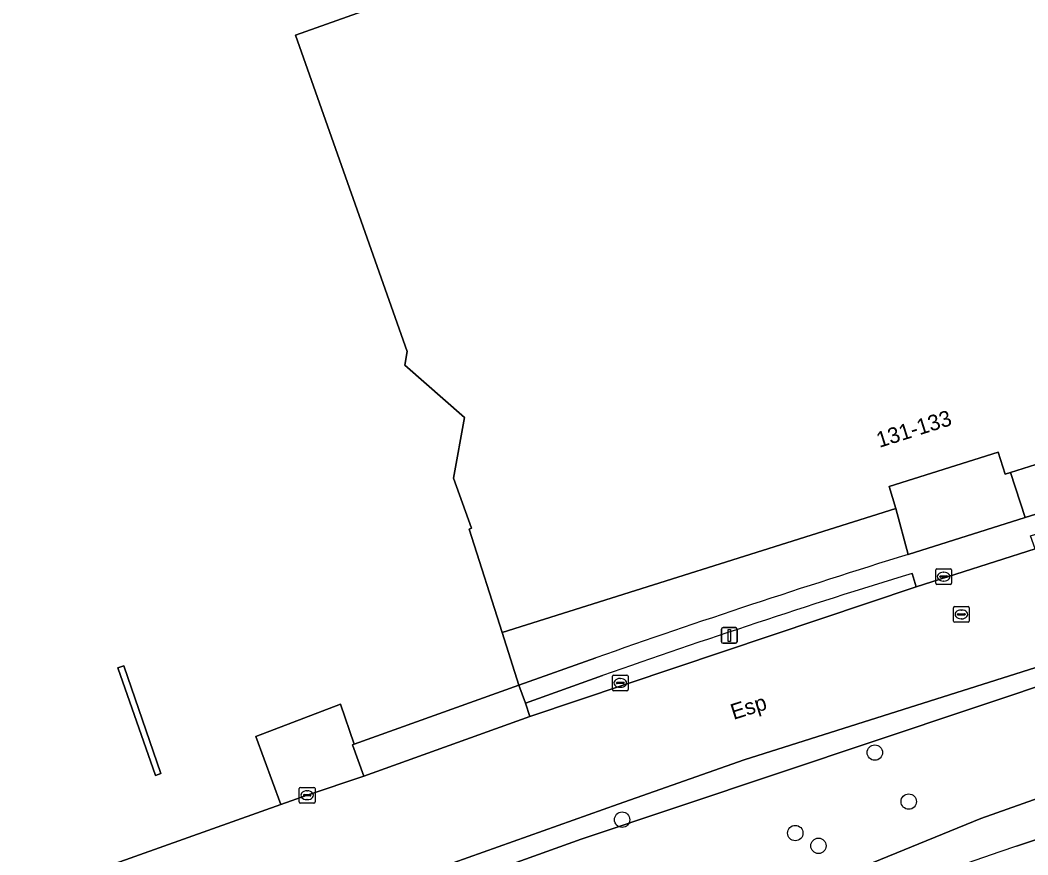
# Model space of a CAD drawing. Extents: x 161385 to 162589, y 388479 to 389756.
# Drawn here: x 162179.9 to 162244, y 388545.6 to 388598.7 of the extents above; entities that cross this region are included whole.
import ezdxf

# ---------------------------------------------------------------- set-up
doc = ezdxf.new("R2010")
doc.units = 0
for name, color, linetype in [('IMGEO_Berm_groen', 7, 'Continuous'), ('IMGEO_Boom', 7, 'Continuous'), ('IMGEO_Erf', 7, 'Continuous'), ('IMGEO_Fietspad_gesloten', 7, 'Continuous'), ('IMGEO_Groenvoorziening', 7, 'Continuous'), ('IMGEO_Kolk', 7, 'Continuous'), ('IMGEO_Lichtmast', 7, 'Continuous'), ('IMGEO_Loofbos', 7, 'Continuous'), ('IMGEO_Muur', 7, 'Continuous'), ('IMGEO_Openbare_ruimte_label', 7, 'Continuous'), ('IMGEO_Pand', 7, 'Continuous'), ('IMGEO_Pand_nummerreeks', 7, 'Continuous'), ('IMGEO_Rijbaan_lokaal_gesloten', 7, 'Continuous'), ('IMGEO_Rioolput', 7, 'Continuous'), ('IMGEO_Voetpad_open', 7, 'Continuous')]:
    doc.layers.add(name, color=color, linetype=linetype)

msp = doc.modelspace()

# ---------------------------------------------------------------- linework, layer by layer
at = {"layer": 'IMGEO_Berm_groen'}
for points in [[(162319.902, 388581.48), (162316.848, 388580.491), (162315.105, 388579.927), (162225.932, 388551.675), (162217.932, 388548.854), (162137.852, 388520.378), (162138.38, 388518.892), (162215.574, 388546.64), (162252.986, 388559.158)], [(162338.365, 388578.901), (162338.047, 388580.195), (162324.599, 388576.081), (162287.169, 388563.505), (162279.038, 388561.214), (162264.796, 388556.642), (162259.025, 388554.101), (162254.71, 388552.825), (162240.969, 388547.955), (162222.876, 388540.549), (162201.4, 388532.175), (162133.055, 388506.534)], [(162243.228, 388546.187), (162337.031, 388577.446)], [(162236.864, 388562.675), (162236.595, 388563.529)], [(162216.931, 388557.029), (162212.031, 388555.28), (162212.321, 388554.419), (162236.864, 388562.675)]]:
    msp.add_lwpolyline(points, dxfattribs=at)
for centre, radius, start, end in [((162387.997, 388072.509), 513.832, 107.13672, 109.44623), ((162557.7, 387632.601), 966.195, 108.994345, 111.094346)]:
    msp.add_arc(centre, radius, start, end, dxfattribs=at)
at = {"layer": 'IMGEO_Boom'}
for centre in [(162234.235, 388552.135), (162236.386, 388549.021), (162218.176, 388547.871), (162229.179, 388547.02), (162230.651, 388546.208)]:
    msp.add_circle(centre, 0.489, dxfattribs=at)
at = {"layer": 'IMGEO_Erf'}
msp.add_lwpolyline([(162178.209, 388542.32), (162196.492, 388548.826), (162194.908, 388553.162), (162200.279, 388555.209), (162201.155, 388552.675), (162211.615, 388556.411), (162210.55, 388559.766), (162208.456, 388566.345), (162208.618, 388566.397), (162207.458, 388569.576), (162208.167, 388573.431), (162204.373, 388576.755), (162204.529, 388577.63), (162197.437, 388597.741), (162253.523, 388617.679), (162265.26, 388584.523), (162265.031, 388584.451), (162268.122, 388574.718), (162279.121, 388578.182), (162278.245, 388581.061), (162278.061, 388581.594), (162278.169, 388581.632), (162249.791, 388661.103)], dxfattribs=at)
msp.add_lwpolyline([(162188.879, 388550.8), (162188.526, 388550.673), (162186.129, 388557.517), (162186.518, 388557.653)], close=True, dxfattribs=at)
at = {"layer": 'IMGEO_Fietspad_gesloten'}
msp.add_lwpolyline([(162337.031, 388577.446), (162243.228, 388546.187)], dxfattribs=at)
msp.add_arc((162557.7, 387632.601), 966.195, 108.994345, 111.094346, dxfattribs=at)
at = {"layer": 'IMGEO_Groenvoorziening'}
for points in [[(162261.864, 388572.748), (162260.965, 388575.651), (162242.86, 388569.947), (162243.781, 388567.084), (162261.644, 388572.678)], [(162200.279, 388555.209), (162194.908, 388553.162), (162196.492, 388548.826), (162198.168, 388549.423), (162201.76, 388550.627), (162201.049, 388552.632), (162201.155, 388552.675)]]:
    msp.add_lwpolyline(points, close=True, dxfattribs=at)
msp.add_lwpolyline([(162236.344, 388564.73), (162235.576, 388567.652), (162210.55, 388559.766), (162211.615, 388556.411), (162216.5, 388558.161)], dxfattribs=at)
msp.add_arc((162400.651, 388035.124), 554.508, 107.23621, 109.39619, dxfattribs=at)
at = {"layer": 'IMGEO_Kolk'}
for p, q in [((162238.103, 388562.895), (162238.103, 388563.747)), ((162238.178, 388563.821), (162239.03, 388563.821)), ((162238.591, 388563.601), (162238.616, 388563.601)), ((162239.104, 388563.747), (162239.104, 388562.895)), ((162239.03, 388562.821), (162238.178, 388562.821)), ((162238.362, 388563.315), (162238.362, 388563.327)), ((162238.8, 388563.278), (162238.402, 388563.278)), ((162238.405, 388563.364), (162238.803, 388563.364)), ((162238.614, 388563.041), (162238.589, 388563.041)), ((162238.846, 388563.327), (162238.846, 388563.315)), ((162217.635, 388557.065), (162218.487, 388557.065)), ((162217.56, 388556.139), (162217.56, 388556.991)), ((162217.819, 388556.559), (162217.819, 388556.571)), ((162218.257, 388556.522), (162217.859, 388556.522)), ((162217.862, 388556.608), (162218.26, 388556.608)), ((162218.048, 388556.845), (162218.073, 388556.845)), ((162218.303, 388556.571), (162218.303, 388556.559)), ((162218.561, 388556.991), (162218.561, 388556.139)), ((162218.487, 388556.065), (162217.635, 388556.065)), ((162218.071, 388556.285), (162218.046, 388556.285)), ((162197.666, 388548.999), (162197.666, 388549.851)), ((162197.741, 388549.925), (162198.593, 388549.925)), ((162197.925, 388549.419), (162197.925, 388549.431)), ((162198.363, 388549.382), (162197.965, 388549.382)), ((162197.968, 388549.468), (162198.366, 388549.468)), ((162198.154, 388549.705), (162198.179, 388549.705)), ((162198.409, 388549.431), (162198.409, 388549.419)), ((162198.667, 388549.851), (162198.667, 388548.999)), ((162198.593, 388548.925), (162197.741, 388548.925)), ((162198.177, 388549.145), (162198.152, 388549.145))]:
    msp.add_line(p, q, dxfattribs=at)
for points in [[(162238.103, 388562.895), (162238.103, 388563.747)], [(162238.178, 388563.821), (162239.03, 388563.821)], [(162239.104, 388563.747), (162239.104, 388562.895)], [(162239.03, 388562.821), (162238.178, 388562.821)], [(162217.635, 388557.065), (162218.487, 388557.065)], [(162217.56, 388556.139), (162217.56, 388556.991)], [(162218.561, 388556.991), (162218.561, 388556.139)], [(162218.487, 388556.065), (162217.635, 388556.065)], [(162197.666, 388548.999), (162197.666, 388549.851)], [(162197.741, 388549.925), (162198.593, 388549.925)], [(162198.667, 388549.851), (162198.667, 388548.999)], [(162198.593, 388548.925), (162197.741, 388548.925)]]:
    msp.add_lwpolyline(points, dxfattribs=at)
for centre, radius, start, end in [((162238.18, 388563.745), 0.0765, 91.55205, 178.44795), ((162238.18, 388563.745), 0.0765, 91.55205, 178.44795), ((162239.028, 388563.745), 0.0765, 1.55205, 88.44795), ((162239.028, 388563.745), 0.0765, 1.55205, 88.44795), ((162238.18, 388562.897), 0.0765, 181.55205, 268.44795), ((162238.18, 388562.897), 0.0765, 181.55205, 268.44795), ((162238.402, 388563.324), 0.0403, 85.87752, 175.75265), ((162238.399, 388563.314), 0.0366, 178.93798, 274.71019), ((162238.803, 388563.321), 0.043, 264.86636, 352.45326), ((162238.807, 388563.326), 0.0386, 1.73085, 96.63898), ((162239.028, 388562.897), 0.0765, 271.55205, 358.44795), ((162239.028, 388562.897), 0.0765, 271.55205, 358.44795), ((162217.637, 388556.989), 0.0765, 91.55205, 178.44795), ((162217.637, 388556.989), 0.0765, 91.55205, 178.44795), ((162218.485, 388556.989), 0.0765, 1.55205, 88.44795), ((162218.485, 388556.989), 0.0765, 1.55205, 88.44795), ((162217.859, 388556.568), 0.0403, 85.87752, 175.75265), ((162217.856, 388556.558), 0.0366, 178.93798, 274.71019), ((162218.26, 388556.565), 0.043, 264.86636, 352.45326), ((162218.264, 388556.57), 0.0386, 1.73085, 96.63898), ((162217.637, 388556.141), 0.0765, 181.55205, 268.44795), ((162217.637, 388556.141), 0.0765, 181.55205, 268.44795), ((162218.485, 388556.141), 0.0765, 271.55205, 358.44795), ((162218.485, 388556.141), 0.0765, 271.55205, 358.44795), ((162197.743, 388549.849), 0.0765, 91.55205, 178.44795), ((162197.743, 388549.849), 0.0765, 91.55205, 178.44795), ((162197.965, 388549.428), 0.0403, 85.87752, 175.75265), ((162197.962, 388549.418), 0.0366, 178.93798, 274.71019), ((162198.366, 388549.425), 0.043, 264.86636, 352.45326), ((162198.37, 388549.43), 0.0386, 1.73085, 96.63898), ((162198.591, 388549.849), 0.0765, 1.55205, 88.44795), ((162198.591, 388549.849), 0.0765, 1.55205, 88.44795), ((162197.743, 388549.001), 0.0765, 181.55205, 268.44795), ((162197.743, 388549.001), 0.0765, 181.55205, 268.44795), ((162198.591, 388549.001), 0.0765, 271.55205, 358.44795), ((162198.591, 388549.001), 0.0765, 271.55205, 358.44795)]:
    msp.add_arc(centre, radius, start, end, dxfattribs=at)
for centre, major_axis, ratio, start_param, end_param in [((162238.59, 388563.321), (-0.387, 0.002), 0.722429, 4.712389, 7.853982), ((162238.615, 388563.321), (-0.39, 0.002), 0.717154, 1.570796, 4.712389), ((162218.047, 388556.565), (-0.387, 0.002), 0.722429, 4.712389, 7.853982), ((162218.072, 388556.565), (-0.39, 0.002), 0.717154, 1.570796, 4.712389), ((162198.153, 388549.425), (-0.387, 0.002), 0.722429, 4.712389, 7.853982), ((162198.178, 388549.425), (-0.39, 0.002), 0.717154, 1.570796, 4.712389)]:
    msp.add_ellipse(centre, major_axis=major_axis, ratio=ratio, start_param=start_param, end_param=end_param, dxfattribs=at)
at = {"layer": 'IMGEO_Lichtmast'}
for p, q in [((162224.491, 388559.182), (162224.491, 388559.982)), ((162224.491, 388559.982), (162224.491, 388559.182)), ((162224.591, 388560.082), (162225.381, 388560.082)), ((162225.381, 388560.082), (162224.591, 388560.082)), ((162225.481, 388559.982), (162225.481, 388559.182)), ((162225.481, 388559.182), (162225.481, 388559.982)), ((162225.381, 388559.082), (162224.591, 388559.082)), ((162224.591, 388559.082), (162225.381, 388559.082))]:
    msp.add_line(p, q, dxfattribs=at)
msp.add_lwpolyline([(162224.911, 388559.957), (162225.061, 388559.957), (162225.061, 388559.207), (162224.911, 388559.207), (162224.911, 388559.957)], dxfattribs=at)
for centre, start, end in [((162224.591, 388559.982), 90, 180), ((162224.591, 388559.982), 90, 180), ((162225.381, 388559.982), 0, 90), ((162225.381, 388559.982), 360, 90), ((162224.591, 388559.182), 180, 270), ((162224.591, 388559.182), 180, 270), ((162225.381, 388559.182), 270, 0), ((162225.381, 388559.182), 270, 0)]:
    msp.add_arc(centre, 0.1, start, end, dxfattribs=at)
at = {"layer": 'IMGEO_Loofbos'}
for points in [[(162336.532, 388584.978), (162317.268, 388578.974), (162288.362, 388570.488), (162252.986, 388559.158), (162215.574, 388546.64), (162138.38, 388518.892), (162124.65, 388513.957), (162116.698, 388511.605), (162115.545, 388511.3), (162114.423, 388510.894), (162113.342, 388510.388), (162112.311, 388509.789), (162111.337, 388509.099), (162110.429, 388508.325), (162110.008, 388507.915), (162109.734, 388507.207), (162110.01, 388506.497), (162110.485, 388506.096), (162117.232, 388501.49), (162117.736, 388502.546)], [(162133.055, 388506.534), (162201.4, 388532.175), (162222.876, 388540.549), (162240.969, 388547.955), (162254.71, 388552.825), (162259.025, 388554.101), (162264.796, 388556.642), (162279.038, 388561.214), (162287.169, 388563.505), (162324.599, 388576.081), (162338.047, 388580.195)]]:
    msp.add_lwpolyline(points, dxfattribs=at)
at = {"layer": 'IMGEO_Muur'}
msp.add_lwpolyline([(162186.129, 388557.517), (162188.526, 388550.673), (162188.879, 388550.8), (162186.518, 388557.653)], close=True, dxfattribs=at)
at = {"layer": 'IMGEO_Pand'}
msp.add_lwpolyline([(162260.965, 388575.651), (162261.059, 388575.681), (162258.904, 388582.531), (162265.031, 388584.451), (162265.26, 388584.523), (162253.523, 388617.679), (162197.437, 388597.741), (162204.529, 388577.63), (162204.373, 388576.755), (162208.167, 388573.431), (162207.458, 388569.576), (162208.618, 388566.397), (162208.456, 388566.345), (162210.55, 388559.766), (162235.576, 388567.652), (162235.134, 388569.054), (162242.071, 388571.243), (162242.515, 388569.838), (162242.86, 388569.947)], close=True, dxfattribs=at)
at = {"layer": 'IMGEO_Rijbaan_lokaal_gesloten'}
for points in [[(162315.105, 388579.927), (162316.848, 388580.491), (162314.748, 388587.303), (162279.715, 388576.261), (162276.796, 388575.341), (162269.879, 388573.06), (162262.278, 388570.688), (162244.409, 388565.088), (162236.864, 388562.675), (162212.321, 388554.419), (162201.76, 388550.627), (162198.168, 388549.423), (162196.492, 388548.826), (162178.209, 388542.32)], [(162134.528, 388526.905), (162135.832, 388519.875), (162137.57, 388520.294), (162137.852, 388520.378), (162217.932, 388548.854), (162225.932, 388551.675), (162315.105, 388579.927)]]:
    msp.add_lwpolyline(points, dxfattribs=at)
at = {"layer": 'IMGEO_Rioolput'}
for p, q in [((162239.233, 388560.493), (162239.233, 388561.345)), ((162239.308, 388561.419), (162240.16, 388561.419)), ((162239.492, 388560.913), (162239.492, 388560.925)), ((162239.93, 388560.876), (162239.532, 388560.876)), ((162239.535, 388560.962), (162239.933, 388560.962)), ((162239.721, 388561.199), (162239.746, 388561.199)), ((162239.976, 388560.925), (162239.976, 388560.913)), ((162240.234, 388561.345), (162240.234, 388560.493)), ((162240.16, 388560.419), (162239.308, 388560.419)), ((162239.744, 388560.639), (162239.719, 388560.639))]:
    msp.add_line(p, q, dxfattribs=at)
for points in [[(162239.233, 388560.493), (162239.233, 388561.345)], [(162239.308, 388561.419), (162240.16, 388561.419)], [(162240.234, 388561.345), (162240.234, 388560.493)], [(162240.16, 388560.419), (162239.308, 388560.419)]]:
    msp.add_lwpolyline(points, dxfattribs=at)
for centre, radius, start, end in [((162239.31, 388561.343), 0.0765, 91.55205, 178.44795), ((162239.31, 388561.343), 0.0765, 91.55205, 178.44795), ((162239.532, 388560.922), 0.0403, 85.87752, 175.75265), ((162239.529, 388560.912), 0.0366, 178.93798, 274.71019), ((162239.933, 388560.919), 0.043, 264.86636, 352.45326), ((162239.937, 388560.924), 0.0386, 1.73085, 96.63898), ((162240.158, 388561.343), 0.0765, 1.55205, 88.44795), ((162240.158, 388561.343), 0.0765, 1.55205, 88.44795), ((162239.31, 388560.495), 0.0765, 181.55205, 268.44795), ((162239.31, 388560.495), 0.0765, 181.55205, 268.44795), ((162240.158, 388560.495), 0.0765, 271.55205, 358.44795), ((162240.158, 388560.495), 0.0765, 271.55205, 358.44795)]:
    msp.add_arc(centre, radius, start, end, dxfattribs=at)
for centre, major_axis, ratio, start_param, end_param in [((162239.72, 388560.919), (-0.387, 0.002), 0.722429, 4.712389, 7.853982), ((162239.745, 388560.919), (-0.39, 0.002), 0.717154, 1.570796, 4.712389)]:
    msp.add_ellipse(centre, major_axis=major_axis, ratio=ratio, start_param=start_param, end_param=end_param, dxfattribs=at)
at = {"layer": 'IMGEO_Voetpad_open'}
for points in [[(162236.595, 388563.529), (162236.864, 388562.675), (162244.409, 388565.088), (162244.127, 388565.914), (162262.005, 388571.529), (162261.644, 388572.678), (162243.781, 388567.084), (162236.344, 388564.73)], [(162216.5, 388558.161), (162211.615, 388556.411), (162212.031, 388555.28), (162216.931, 388557.029)]]:
    msp.add_lwpolyline(points, dxfattribs=at)
for points in [[(162243.781, 388567.084), (162242.86, 388569.947), (162242.515, 388569.838), (162242.071, 388571.243), (162235.134, 388569.054), (162235.576, 388567.652), (162236.344, 388564.73)], [(162201.76, 388550.627), (162212.321, 388554.419), (162212.031, 388555.28), (162211.615, 388556.411), (162201.155, 388552.675), (162201.049, 388552.632)]]:
    msp.add_lwpolyline(points, close=True, dxfattribs=at)
for centre, radius, start, end in [((162400.651, 388035.124), 554.508, 107.23621, 109.39619), ((162387.997, 388072.509), 513.832, 107.13672, 109.44623)]:
    msp.add_arc(centre, radius, start, end, dxfattribs=at)

# ---------------------------------------------------------------- texts
at = {"layer": 'IMGEO_Openbare_ruimte_label'}
msp.add_text('Esp', height=1, rotation=17.5831, dxfattribs=at).set_placement((162225.259, 388554.211))
at = {"layer": 'IMGEO_Pand_nummerreeks'}
msp.add_text('131-133', height=1, rotation=17.51331, dxfattribs=at).set_placement((162234.522, 388571.503))

doc.saveas('drawing.dxf')
